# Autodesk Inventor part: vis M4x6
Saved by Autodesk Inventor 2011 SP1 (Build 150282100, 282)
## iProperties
Created: 2010-12
Part Number: vis M4x6
Document SubType Name: Modeling
Designer: eric
Density: 1 g/cm^3
Author: eric
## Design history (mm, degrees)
feature "Base1"
node "Solide1"
node "Corps solides"
node "Corps surfaciques"
